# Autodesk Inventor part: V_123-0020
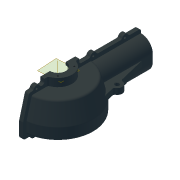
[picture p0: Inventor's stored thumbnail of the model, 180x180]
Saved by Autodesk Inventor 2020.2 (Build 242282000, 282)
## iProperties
Created: 2006-02
Part Number: V_123-0020
Document SubType Name: Modeling
Designer: F.Stasiak
Description: Obudowa - lewa
Material: L450
Project: Przekładnia X51
Mass: 3378.1 g
Surface Area: 1383.4 cm^2
Volume: 465.945 cm^3
Density: 7.25 g/cm^3
Appearance: Brąz armatni (nowy/polerowany)
Manager: www.cadconsulting.pl
Company: Fabian Stasiak CAD Consulting
Author: F.Stasiak
Subject: Zbiór ćwiczeń. Autodesk Inventor 2020. Kurs podstawowy
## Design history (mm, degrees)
derived "V_123-0010.ipt"
  node "Płaszczyzna konstrukcyjna1"
  node "Płaszczyzna konstrukcyjna2"
  node "Płaszczyzna konstrukcyjna4"
  node "Oś konstrukcyjna1"
node "Bryła1"
node "Korpusy bryłowe"
node "Korpusy powierzchniowe"
tag "Bryła wyprowadzona2"
node "Płaszczyzna konstrukcyjna5"
node "Płaszczyzna konstrukcyjna3"
feature "DerivedBody::V_123-0010.ipt"
